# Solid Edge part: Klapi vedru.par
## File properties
Author: Türk
Template: NORMMET.PAR
Last saved by: Türk
Revision: 25
Application: Solid Edge
Material: Steel
Face Style: Steel
Fill Style: ANSI32(Steel)
Virtual Style: Machined steel
Coef. of Thermal Exp: 1.3e-05
Thermal Conductivity: 32.0
Specific Heat: 481.0
Modulus of Elasticity: 199947953000.0
Poission's Ratio: 0.29
Yield Stress: 262000766.0
Ultimate Stress: 358527364.0
Elongation: 0.0
Density: 0,000007833 kg/mm^3
Accuracy: 0,99
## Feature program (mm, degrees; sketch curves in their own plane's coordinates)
helix protrusion "HelixProtrusion_1"  n = 5
sketch for "unnamed Cutout 1" plane through (0, 0, 0) normal (0, -1, 0) x-axis (1, 0, 0)
  line (0, 24.5) -> (0, -24.5)
  line (0, -24.5) -> (-8, -24.5)
  line (-8, -24.5) -> (-8, 24.5)
  line (-8, 24.5) -> (0, 24.5)
  dimension (linear) = 8
extrude "unnamed Cutout 1" cut finite 24.5 symmetric
sketch for "ExtrudedCutout_3" plane through (0, 0, 0) normal (0, -1, 0) x-axis (1, 0, 0)
  line (17, 24.5) -> (17, -24.5)
  line (17, -24.5) -> (25, -24.5)
  line (25, -24.5) -> (25, 24.5)
  line (25, 24.5) -> (17, 24.5)
  dimension (linear) = 25
extrude "ExtrudedCutout_3" cut finite 24.5 symmetric
base feature "unnamed BaseFeature 1"
sketch for "unnamed Protrusion 1" plane through (0, 0, 0) normal (1, 0, 0) x-axis (0, 1, 0)
extrude "unnamed Protrusion 1" add along +normal
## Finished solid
Body 1: solid body, 3 faces, 2 edges, 0 vertices.
  Faces by surface: plane 2, spline 1
  Edges by curve: intersection 2
Bounding box of the edges (mm; curved faces can reach further): 17.000 x 19.333 x 18.336, from (0, -9.6667, -9.6664) to (17, 9.6665, 8.6699).
Planar faces by outward normal: +x 1, -x 1
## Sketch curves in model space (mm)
circle centre (0, 0, 0) radius 8.75
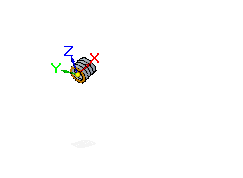
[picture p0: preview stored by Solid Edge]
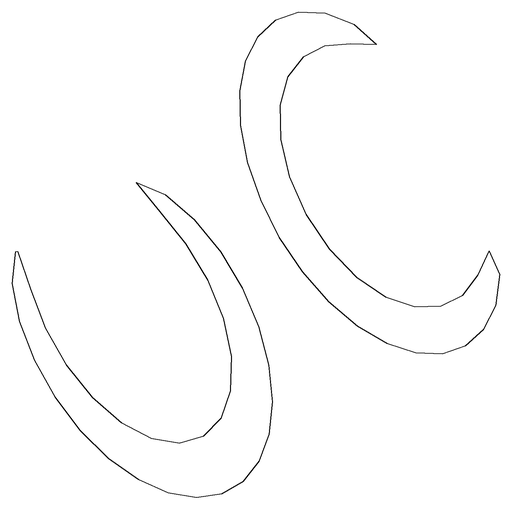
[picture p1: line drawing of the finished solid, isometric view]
